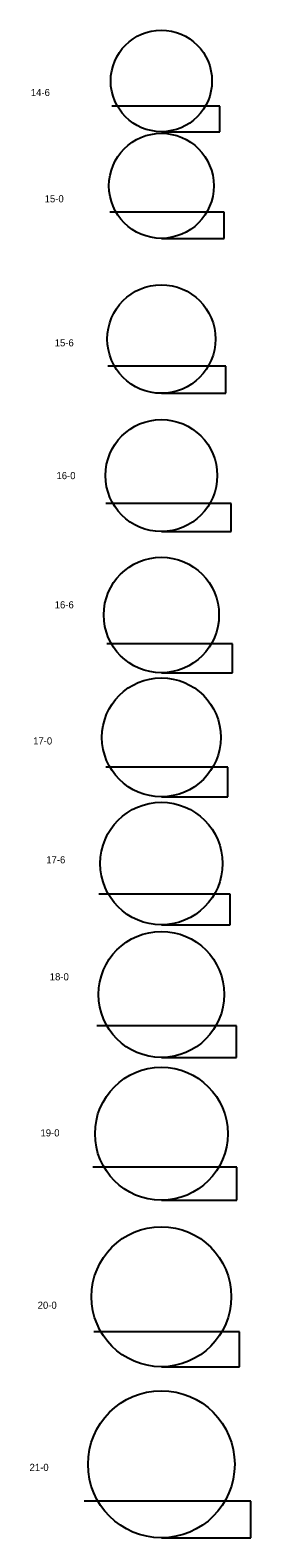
# Model space of a CAD drawing. Extents: x 49957 to 50021, y 49577 to 50011.
# Drawn here: x 49957.1 to 49988.7, y 49577.1 to 49792.4 of the extents above; entities that cross this region are included whole.
import ezdxf

# ---------------------------------------------------------------- set-up
doc = ezdxf.new("R2010")
doc.units = 0
doc.layers.add('Level 2', color=7, linetype='Continuous')

msp = doc.modelspace()

# ---------------------------------------------------------------- linework, layer by layer
at = {"layer": 'Level 2'}
for p, q in [((49984.23, 49781.52), (49968.78, 49781.52)), ((49984.23, 49777.89), (49984.23, 49781.52)), ((49975.87, 49777.89), (49984.23, 49777.89)), ((49984.84, 49766.41), (49968.51, 49766.41)), ((49984.84, 49762.66), (49984.84, 49766.41)), ((49975.87, 49762.66), (49984.84, 49762.66)), ((49985.11, 49744.4), (49968.21, 49744.4)), ((49985.11, 49740.53), (49985.11, 49744.4)), ((49975.87, 49740.53), (49985.11, 49740.53)), ((49985.85, 49724.78), (49967.94, 49724.78)), ((49985.85, 49720.78), (49985.85, 49724.78)), ((49975.87, 49720.78), (49985.85, 49720.78)), ((49986.07, 49704.75), (49968.07, 49704.75)), ((49986.07, 49700.63), (49986.07, 49704.75)), ((49975.87, 49700.63), (49986.07, 49700.63)), ((49985.41, 49687.15), (49967.9, 49687.15)), ((49985.41, 49682.9), (49985.41, 49687.15)), ((49975.87, 49682.9), (49985.41, 49682.9)), ((49985.72, 49669), (49966.93, 49669)), ((49985.72, 49664.63), (49985.72, 49669)), ((49975.87, 49664.63), (49985.72, 49664.63)), ((49986.64, 49650.19), (49966.63, 49650.19)), ((49986.64, 49645.69), (49986.64, 49650.19)), ((49975.87, 49645.69), (49986.64, 49645.69)), ((49986.68, 49630.04), (49966.04, 49630.04)), ((49986.68, 49625.29), (49986.68, 49630.04)), ((49975.87, 49625.29), (49986.68, 49625.29)), ((49987.07, 49606.52), (49966.22, 49606.52)), ((49987.07, 49601.52), (49987.07, 49606.52)), ((49975.87, 49601.52), (49987.07, 49601.52)), ((49988.69, 49582.34), (49964.81, 49582.34)), ((49988.69, 49577.09), (49988.69, 49582.34)), ((49975.87, 49577.09), (49988.69, 49577.09))]:
    msp.add_line(p, q, dxfattribs=at)
for centre, radius in [((49975.87, 49785.14), 7.25), ((49975.87, 49770.16), 7.5), ((49975.87, 49748.28), 7.75), ((49975.87, 49728.78), 8), ((49975.87, 49708.88), 8.25), ((49975.87, 49691.4), 8.5), ((49975.87, 49673.38), 8.75), ((49975.87, 49654.69), 9), ((49975.87, 49634.79), 9.5), ((49975.87, 49611.52), 10), ((49975.87, 49587.59), 10.5)]:
    msp.add_circle(centre, radius, dxfattribs=at)

# ---------------------------------------------------------------- texts
for s, p in [('14-6', (49957.18, 49782.98)), ('15-0', (49959.16, 49767.8)), ('15-6', (49960.6, 49747.23)), ('16-0', (49960.85, 49728.27)), ('16-6', (49960.6, 49709.82)), ('17-0', (49957.51, 49690.38)), ('17-6', (49959.39, 49673.41)), ('18-0', (49959.89, 49656.7)), ('19-0', (49958.56, 49634.41)), ('20-0', (49958.16, 49609.8)), ('21-0', (49957, 49586.64))]:
    msp.add_text(s, height=1.019, dxfattribs=at).set_placement(p)

doc.saveas('drawing.dxf')
